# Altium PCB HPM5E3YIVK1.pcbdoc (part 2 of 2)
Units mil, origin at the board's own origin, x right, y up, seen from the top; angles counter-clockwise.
Board outline 3937 x 3149.7 mil, 6 copper layers (Top Layer, Inner1, Inner2, Inner3, Inner4, Bottom Layer), stack 60.7 mil thick; 242 components, 203 nets, 838 pads, 137 vias.
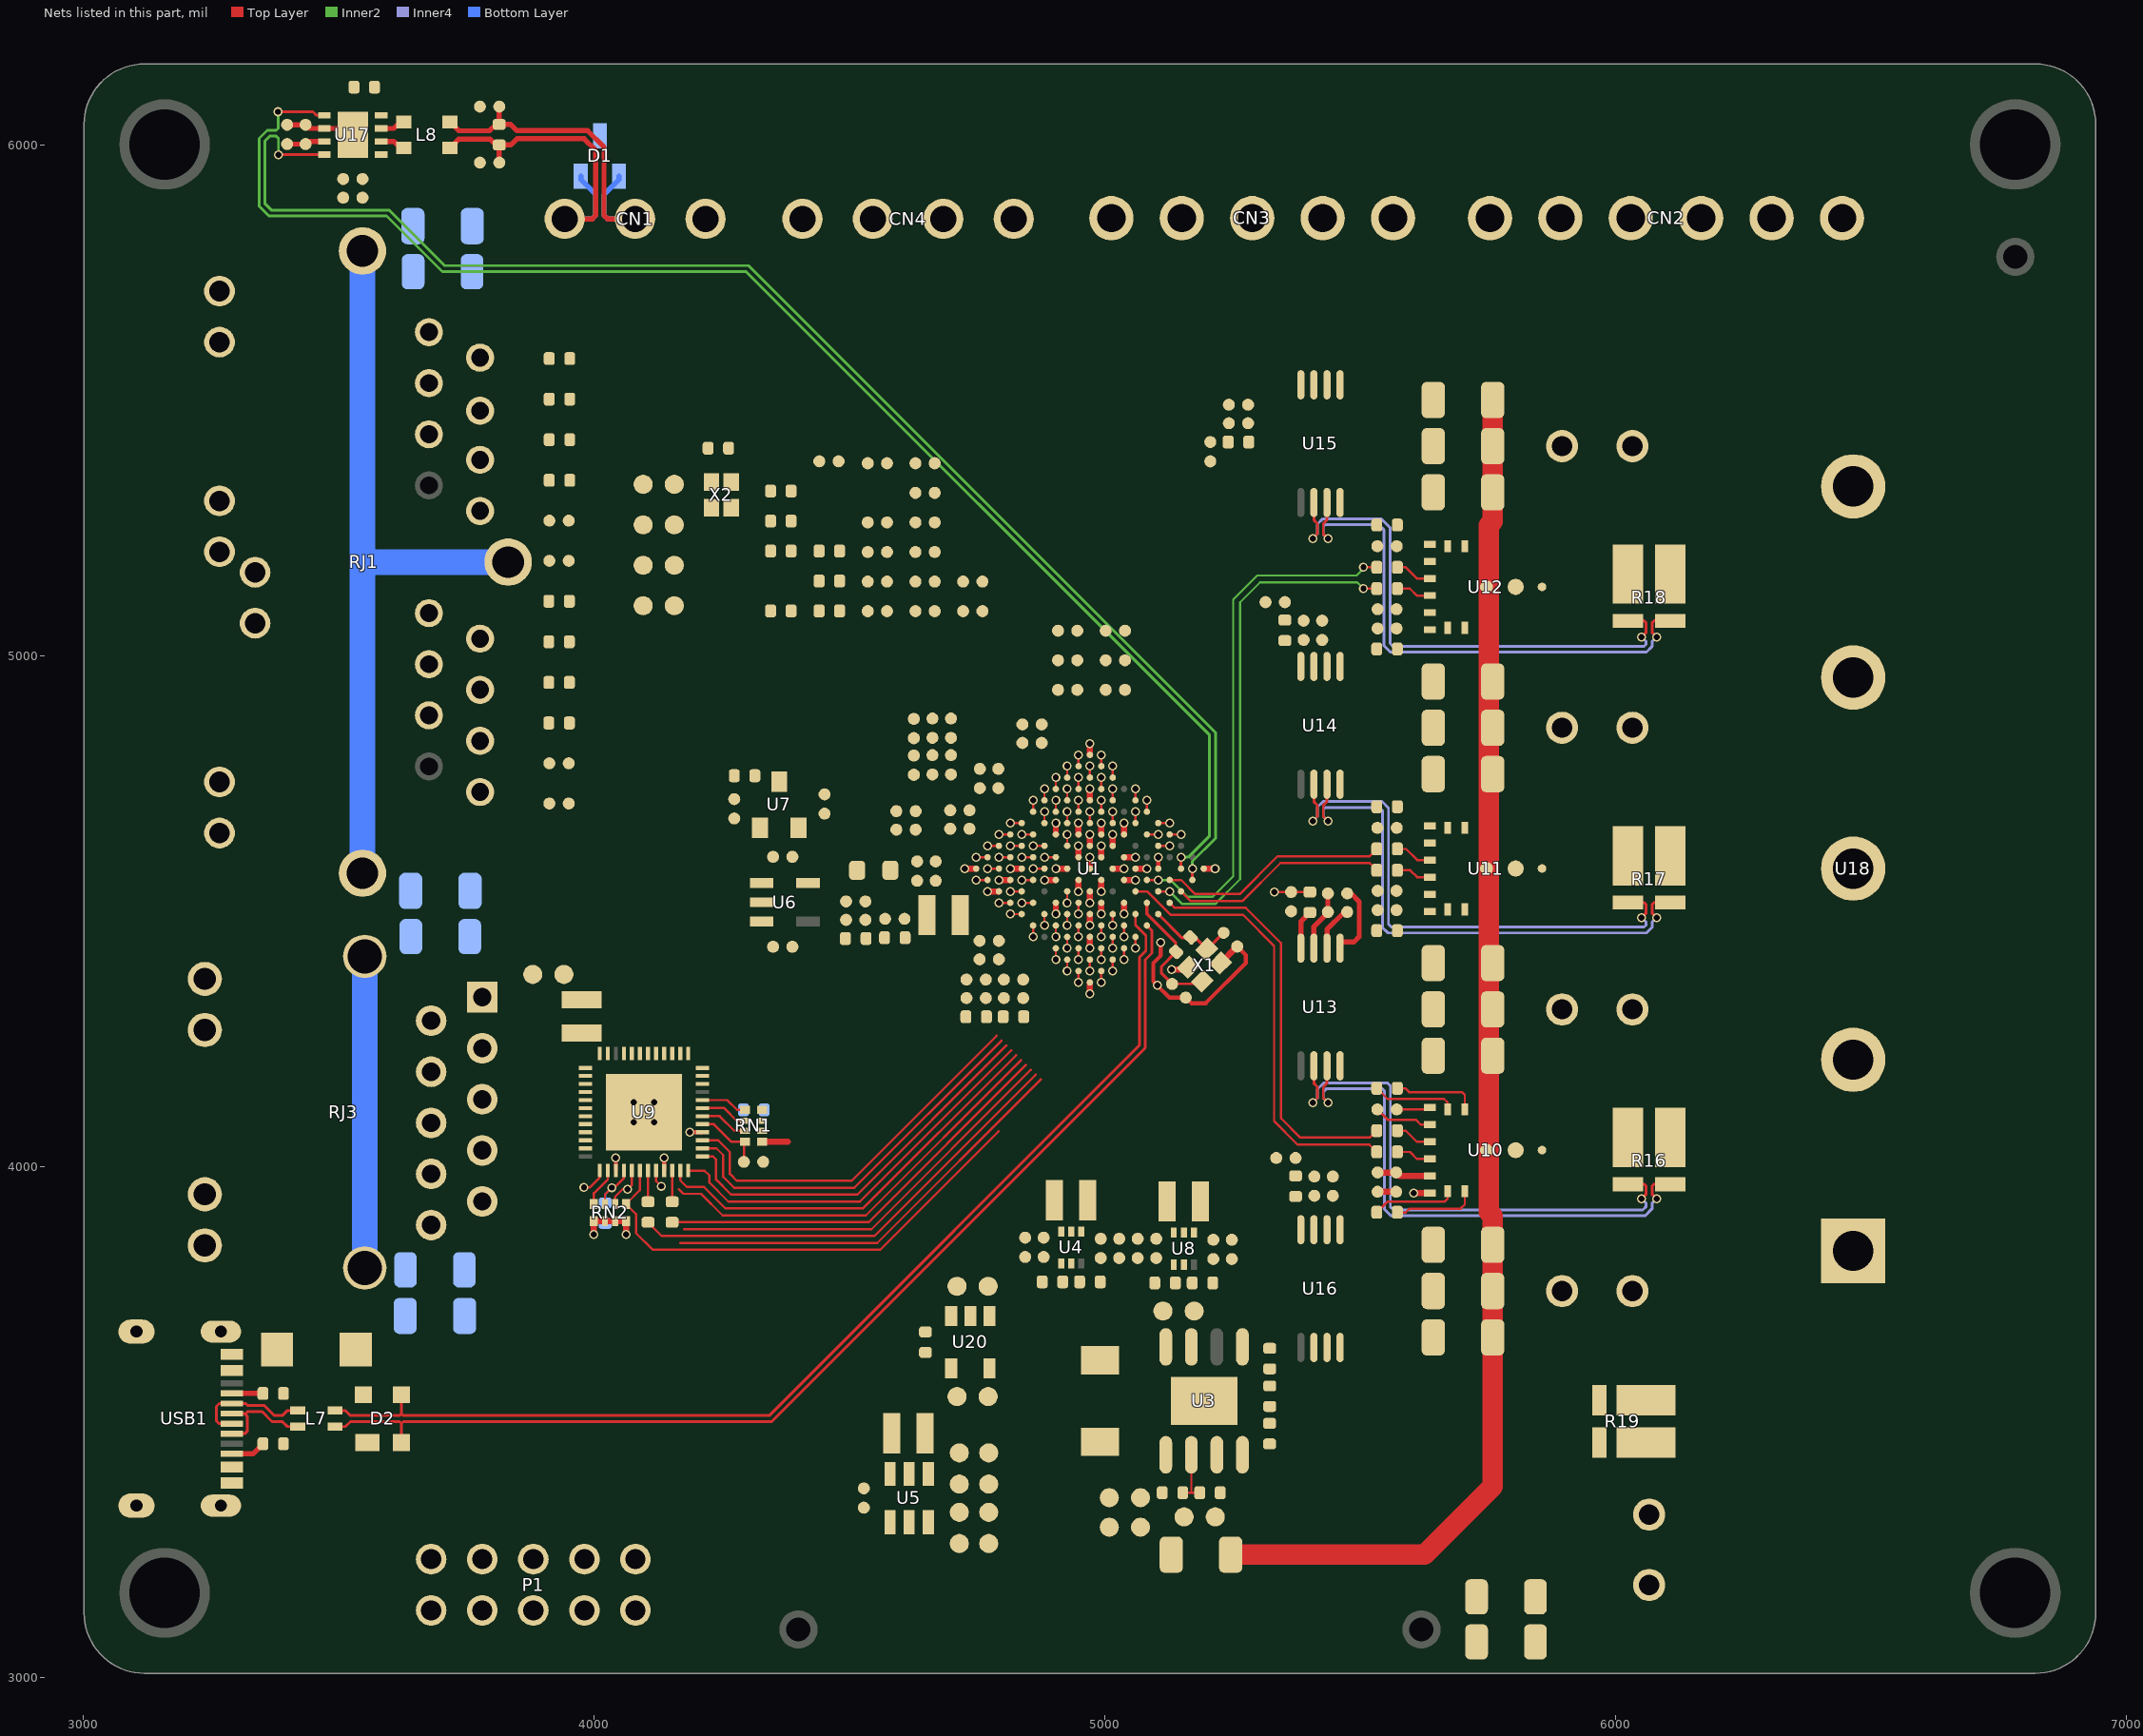
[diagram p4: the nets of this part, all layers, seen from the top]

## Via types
v1: diameter 17.7, hole 12, Top Layer to Bottom Layer, 133 vias
v2: diameter 24, hole 12, Top Layer to Bottom Layer, 4 vias

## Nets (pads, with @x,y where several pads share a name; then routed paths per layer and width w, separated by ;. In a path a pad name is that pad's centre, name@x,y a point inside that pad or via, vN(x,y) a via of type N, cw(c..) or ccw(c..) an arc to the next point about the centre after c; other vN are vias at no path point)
5V: C40.1 C41.1 C125.1 D2.4 D3.1 L3.2 U5.1 U20.5
$1N77: C3.1 C4.1 FB1.1 U1.K2 U1.L2 | length 44.6
  Top Layer w4.5: v1(4748.2,4561.5) U1.L2@4770.5,4561.5 ; v1(4770.5,4583.7) U1.K2@4792.8,4583.7
$1N85: C7.1 C8.1 FB2.1 U1.H6 | length 22.3
  Top Layer w4.5: v1(4926.4,4516.9) U1.H6@4926.4,4539.2
$1N89: C9.1 R3.1
$1N91: C10.1 C11.1 FB3.2 U1.H7 | length 22.2
  Top Layer w4.5: v1(4948.6,4494.7) U1.H7@4948.6,4516.9
$1N106: C26.1 C27.1 U1.H4 | length 22.2
  Top Layer w4.5: v1(4859.6,4583.7) U1.H4@4881.8,4583.7
$1N108: C28.1 C29.1 U1.F4 | length 22.2
  Top Layer w4.5: U1.F4@4926.4,4628.3 v1(4926.4,4650.5)
$1N110: C30.1 C31.1 U1.G4 | length 22.3
  Top Layer w4.5: v1(4881.8,4606) U1.G4@4904.1,4606
$1N112: C32.1 C33.1 U1.D4 | length 22.3
  Top Layer w4.5: U1.D4@4970.9,4672.8 v1(4970.9,4695.1)
$3N8: R5.2 R6.1 U3.2 | length 107.5
  Top Layer w4.5: R6.1@5152.6,3362.3 5168.9,3362.3 ; U3.2@5169.3,3436.5 5169.3,3362.7 5168.9,3362.3 ; R5.2@5185.7,3362.3 5168.9,3362.3
$3N11: R7.1 U3.4
$3N13: C36.1 L2.1 U3.8
$3N15: C36.2 U3.7
$3N18: R8.1 R9.2 U3.5
$3N20: C39.2 L3.1 U5.5
$3N21: C39.1 U5.6
$3N27: L4.1 U4.2
$3N34: R10.2 R11.2 U4.5
$3N48: R12.2 R13.2 U8.5
$3N54: L5.1 U8.2
$3N62: R61.1 U20.3
$4N84: C56.1 RJ1.A4
$4N85: C57.1 RJ1.A5
$4N86: C62.1 RJ1.B4
$4N87: C63.1 RJ1.B5
$4N90: R20.1 RJ1.A9
$4N92: R22.1 RJ1.A11
$4N94: R24.1 RJ1.B9
$4N96: R26.1 RJ1.B11
$5N100: L6.1 U9.48
$5N112: R28.1 U9.38
$5N113: R29.1 U9.39
$5N117: C70.2 R30.2 U9.42 X2.3
$5N150: R31.2 U9.19 | length 60.9
  Top Layer w4.5: R31.2@4106,3931.7 U9.19@4106,3992.6
$5N152: R32.2 U9.22 | length 60.9
  Top Layer w4.5: R32.2@4153.2,3931.7 U9.22@4153.2,3992.6
$5N166: R33.2 RJ3.12
$5N169: R36.2 RJ3.13
$5N190: C80.2 RJ3.P1
$5N214: C71.2 R30.1 U9.43 X2.1
$6N1: R16.2 U10.9
$6N2: R17.2 U11.9
$6N3: R18.2 U12.9
$6N4: C89.2 U10.25 | length 66.1
  Top Layer w4.5: C89.2@5571.3,4112.4 5632,4112.4 U10.25@5635.9,4116.2
$6N5: C89.1 U10.26 | length 114.7
  Top Layer w4.5: C89.1@5533.5,4112.4 5553.5,4092.3 5608.6,4092.3 5618.2,4082.8 U10.26@5635.9,4082.8
$6N6: R43.2 U10.23 | length 165.5
  Top Layer w4.5: R43.2@5572.5,4153.7 5588.2,4153.7 5595.5,4146.4 5698.8,4146.4 5704.5,4140.7 U10.23@5704.5,4112.6
$6N7: R43.1 U10.24 | length 163.6
  Top Layer w4.5: R43.1@5532.3,4153.7 5553.2,4132.9 5664.2,4132.9 5671.1,4126 U10.24@5671.1,4112.6
$6N8: R44.1 U10.1 | length 164.3
  Top Layer w4.5: R44.1@5532.3,3911.2 5552.8,3931.7 5664.4,3931.7 5671.1,3938.3 U10.1@5671.1,3952.6
$6N9: R44.2 U10.2 | length 165.8
  Top Layer w4.5: R44.2@5571.6,3910.5 5588.8,3910.5 5596.4,3918.2 5696.4,3918.2 5704.5,3926.3 U10.2@5704.5,3952.6
$6N26: R47.1 U11.24
$6N27: R48.1 U11.1
$6N28: R47.2 U11.23
$6N29: R48.2 U11.2
$6N30: C91.1 U11.26
$6N31: C91.2 U11.25
$6N39: R51.1 U12.24
$6N40: R52.1 U12.1
$6N41: R51.2 U12.23
$6N42: R52.2 U12.2
$6N43: C93.1 U12.26
$6N44: C93.2 U12.25
$6N51: R45.1 U10.27 | length 72.4
  Top Layer w4.5: R45.1@5572.5,4071 5588.8,4071 5610.5,4049.3 U10.27@5635.9,4049.3
$6N52: R46.1 U10.28 | length 69
  Top Layer w4.5: R46.1@5572.5,4029.3 5597.2,4029.3 5610.7,4015.8 U10.28@5635.9,4015.8
$6N54: R49.1 U11.27 | length 72.4
  Top Layer w4.5: R49.1@5572.5,4622.2 5589.5,4622.2 5611.2,4600.5 U11.27@5635.9,4600.5
$6N55: R50.1 U11.28 | length 69
  Top Layer w4.5: R50.1@5572.5,4580.5 5597.7,4580.5 5611.2,4567 U11.28@5635.9,4567
$6N57: R53.1 U12.27 | length 72.4
  Top Layer w4.5: R53.1@5572.5,5173.4 5589,5173.4 5610.7,5151.7 U12.27@5635.9,5151.7
$6N58: R54.1 U12.28 | length 69
  Top Layer w4.5: R54.1@5572.5,5131.7 5597.1,5131.7 5610.5,5118.2 U12.28@5635.9,5118.2
$7N5: R55.2 U13.8 | length 64.9
  Top Layer w10: U13.8@5383.6,4440.2 5383.6,4480.1 R55.2@5401.2,4497.8
$7N38: C97.1 R55.1 | length 69.2
  Top Layer w4.5: v1(5332,4537.9) C97.1@5364.6,4537.9 R55.1@5401.2,4537.9
$7N41: C100.1 R56.1
$7N49: R56.2 U14.8
$7N52: C103.1 R57.1
$7N60: R57.2 U15.8
$7N63: C106.1 R58.1
$7N71: R58.2 U16.8
$8N9: R59.2 USB1.A5 | length 60.6
  Top Layer w10: USB1.A5@3291.7,3556.6 R59.2@3352.3,3556.6
$8N10: R60.2 USB1.B5 | length 68.8
  Top Layer w10: USB1.B5@3291.7,3438.4 3332.6,3438.4 R60.2@3352.3,3458.1
$8N21: L7.1 USB1.A7 USB1.B7 | length 236.5
  Top Layer w5.5: USB1.A7@3291.7,3497.5 3266.8,3497.5 3261.3,3502.9 3261.3,3531.4 3266.8,3536.9 USB1.B7@3291.7,3536.9 3318.9,3536.9 3323,3532.8 3355.1,3532.8 3374.8,3513.2 3390.3,3513.2 3400.3,3523.2 L7.1@3420.5,3523.2
$8N22: L7.4 USB1.A6 USB1.B6 | length 211.7
  Top Layer w5.5: USB1.B6@3291.7,3477.8 3316.6,3477.8 3322.1,3483.3 3322.1,3511.4 3316.4,3517.2 ; USB1.A6@3291.7,3517.2 3316.4,3517.2 ; L7.4@3420.5,3491.7 3400.3,3491.7 3390.3,3501.7 3370,3501.7 3350.4,3521.3 3323,3521.3 3318.9,3517.2 3316.4,3517.2
$9N1: P1.7
$9N2: P1.3
$9N4: P1.1
$9N5: P1.9
$9N6: P1.5
$9N7: P1.2
$9N8: P1.8
$9N9: P1.10
$9N10: P1.4
$9N11: P1.6
$10N3: R41.2 U17.8
$10N15: L8.2 U17.6 | length 49.2
  Top Layer w10: U17.6@3583.9,6006.8 3608.3,6006.8 3621.1,5994 L8.2@3627.8,5994
$10N16: L8.1 U17.7 | length 49.1
  Top Layer w10: U17.7@3583.9,6032.4 3608.3,6032.4 3621.1,6045.1 L8.1@3627.8,6045.1
+1.0V: C58.1 C59.1 C60.1 C61.1 C66.1 C67.1 C68.1 C69.1 L6.2 U9.3 U9.9 U9.28 U9.36 U9.40 | length 24.9
  Top Layer w8: v1(4187.7,4067.6) 4212.5,4067.6 U9.28@4212.6,4067.7
+1.25V: C54.2 C55.2 L5.2 R12.1
+3.3V: C18.1 C19.1 C20.1 C21.1 C22.1 C23.1 C24.1 C25.1 C46.2 C47.2 C52.1 C53.1 C72.1 C73.1 C74.1 C75.1 C76.1 C77.1 C78.1 C79.1 C83.1 C84.1 FB1.2 L4.2 R10.1 R28.2 R35.2 R38.2 RJ3.14 RN1.1 RN1.2 RN1.3 RN1.4 RN2.1 RN2.2 RN2.3 RN2.4 U1.D7 U1.D8 U1.E4 U1.E8 U1.G8 U1.H5 U8.3 U8.4 U9.6 U9.15 U9.21 U9.37 U9.41 U9.44 U9.45 U17.5 | length 348.8
  Top Layer w8: U9.15@4043,3992.6 v1(4043,4017.4) ; U9.21@4137.5,3992.6 v1(4137.5,4017.5)
  Top Layer w12: v1(4000.1,3867.6) RN2.4@4000.1,3893.7 RN2.3@4021.7,3893.7 RN2.2@4041.4,3893.7 RN2.1@4063.1,3893.7 v1(4063.1,3867.6) ; RN1.4@4329.3,4049 4379.5,4049 ; v1(4881.8,4561.5) U1.H5@4904.1,4561.5 ; U1.E4@4948.6,4650.5 v1(4948.6,4672.8) ; v1(4993.2,4494.7) U1.G8@4993.2,4516.9 ; U1.E8@5037.7,4561.5 v1(5060,4561.5) ; U1.D7@5037.7,4606 v1(5060,4606) ; U1.D8@5060,4583.7 v1(5082.3,4583.7)
+3.3VA: C49.1 C95.1 C98.1 C101.1 C104.1 FB2.2 U6.5 U13.5 U14.5 U15.5 U16.5 | length 140.4
  Top Layer w10: U13.5@5460.4,4440.2 5487.6,4440.2 5497.9,4450.5 5497.9,4518.9 5481.6,4535.2 C95.1@5474.4,4535.2
+3.3VREF: C50.1 C96.1 C99.1 C102.1 C105.1 FB3.1 U7.2 U13.6 U14.6 U15.6 U16.6 | length 78.3
  Top Layer w10: U13.6@5434.8,4440.2 5434.8,4464.8 5468.8,4498.8 C96.1@5474.4,4498.8
+5V: C44.1 C45.1 C48.1 C51.1 C85.1 C86.1 C90.1 C92.1 C94.1 C124.1 C126.1 C127.1 C128.1 CN2.1 CN3.1 CN4.4 U4.3 U4.4 U6.1 U6.3 U7.1 U10.29 U11.29 U12.29 U17.3 U20.1 | length 184
  Top Layer w10: C86.1@3399.6,6001.7 C85.1@3435.8,6001.7 3440.9,6006.8 U17.3@3472.7,6006.8
  Top Layer w12: C126.1@5529.9,3989.1 C90.1@5570.2,3989.1 5576.9,3982.4 U10.29@5635.9,3982.4
+12V: C37.1 C38.1 C42.2 C43.2 L2.2 R8.2 U5.2 U5.3
ADC0.IN00: CN4.3 U1.K8 | length 22.3
  Top Layer w4.5: v1(4926.4,4427.8) U1.K8@4926.4,4450.1
ADC0.IN01: U1.L6 | length 22.3
  Top Layer w4.5: v1(4859.6,4450.1) U1.L6@4859.6,4472.4
ADC0.IN02: U1.J8 | length 22.3
  Top Layer w4.5: v1(4948.6,4450.1) U1.J8@4948.6,4472.4
ADC0.IN03: U1.L5 | length 22.3
  Top Layer w4.5: v1(4815,4494.7) U1.L5@4837.3,4494.7
ADC0.IN08: U1.K6 | length 22.3
  Top Layer w4.5: v1(4881.8,4472.4) U1.K6@4881.8,4494.7
ADC0.IN10: U1.K7 | length 22.3
  Top Layer w4.5: v1(4904.1,4450.1) U1.K7@4904.1,4472.4
ADC0.IN13: CN4.2 U1.K5 | length 22.3
  Top Layer w4.5: v1(4837.3,4516.9) U1.K5@4859.6,4516.9
ADC0.IN14: U1.L8 | length 22.2
  Top Layer w4.5: v1(4904.1,4405.6) U1.L8@4904.1,4427.8
ADC0.IN15: U1.J7 | length 22.2
  Top Layer w4.5: v1(4926.4,4472.4) U1.J7@4926.4,4494.6
AGND: C7.2 C8.2 C10.2 C11.2 C48.2 C49.2 C50.2 C51.2 C95.2 C96.2 C97.2 C98.2 C99.2 C100.2 C101.2 C102.2 C103.2 C104.2 C105.2 C106.2 CN4.1 R4.2 U1.G7 U1.H8 U6.2 U7.3 U13.4 U13.7 U14.4 U14.7 U15.4 U15.7 U16.4 U16.7 | length 150.9
  Top Layer w10: U13.7@5409.2,4440.2 5409.2,4470.1 5436.6,4497.5 C95.2@5436.6,4535.2
  Top Layer w12: v1(4970.9,4472.4) U1.H8@4970.9,4494.7 ; v1(4970.9,4516.9) U1.G7@4970.9,4539.2
BOOT0: U1.C2 | length 22.3
  Top Layer w4.5: U1.C2@4948.6,4739.6 v1(4948.6,4761.9)
BOOT1: U1.B1 | length 22.2
  Top Layer w4.5: U1.B1@4948.6,4784.2 v1(4948.6,4806.4)
CAN_H: C87.2 CN1.2 D1.1 L8.4 R42.1 | length 710.7
  Top Layer w10: L8.4@3718.1,6045.1 3735.7,6027.6 3795.8,6027.6 R42.1@3808.3,6040.1 ; C87.2@3814.9,6075 R42.1@3814.9,6040.1 3837.5,6040.1 3849.6,6028 3987.7,6028 4019.8,5995.9 4019.8,5862.4 4026.9,5855.3 CN1.2@4080.7,5855.3
  Bottom Layer w10: D1.1@4049.2,5939 4049.2,5932.4 4019.8,5903 4019.8,5862.4 4026.9,5855.3 CN1.2@4080.7,5855.3
CAN_L: C88.2 CN1.3 D1.2 L8.3 R42.2 | length 683.6
  Top Layer w10: L8.3@3718.1,5994 3735.7,6011.6 3796.6,6011.6 R42.2@3808.3,5999.9 ; C88.2@3814.9,5965.4 R42.2@3814.9,5999.9 3837.5,5999.9 3849.6,6012 3981.1,6012 4003.8,5989.3 4003.8,5862.4 3996.8,5855.3 CN1.3@3942.9,5855.3
  Bottom Layer w10: CN1.3@3942.9,5855.3 3996.8,5855.3 4003.8,5862.4 4003.8,5903 3974.4,5932.4 D1.2@3974.4,5939
DCDC_GND: C3.2 C4.2 C9.2 R2.2 U1.K3 U1.L3 | length 44.4
  Top Layer w12: v1(4770.5,4539.2) U1.L3@4792.7,4539.2 ; v1(4792.8,4561.5) U1.K3@4815,4561.5
DCDC_LP: L1.2 R3.2 U1.K4 U1.L4 | length 44.5
  Top Layer w4.5: v1(4792.8,4516.9) U1.L4@4815,4516.9 ; v1(4815,4539.2) U1.K4@4837.3,4539.2
ESC0_MDC: RN1.6 U1.D3 U9.30 | length 117.1
  Top Layer w4.5: U9.30@4212.6,4099.2 4246.3,4099.2 4275,4070.6 RN1.6@4295.6,4070.6 ; U1.D3@4948.6,4695.1 v1(4948.6,4717.4)
ESC0_MDIO: RN1.7 U1.D2 U9.31 | length 115.4
  Top Layer w4.5: U9.31@4212.6,4115 4255,4115 4279.7,4090.3 RN1.7@4295.6,4090.3 ; U1.D2@4926.4,4717.4 v1(4926.4,4739.6)
ESC0_P0_LED0: R25.1 RJ1.B10 U1.E3 | length 22.3
  Top Layer w4.5: U1.E3@4926.4,4672.8 v1(4926.4,4695.1)
ESC0_P0_LED1: R26.2 R27.2 U1.E2 | length 22.3
  Top Layer w4.5: U1.E2@4904.1,4695.1 v1(4904.1,4717.4)
ESC0_P0_RB: U1.E1 | length 22.2
  Top Layer w4.5: U1.E1@4881.8,4717.4 v1(4881.8,4739.6)
ESC0_P0_RXN: RJ1.B6 U1.H2 | length 22.3
  Top Layer w4.5: v1(4815,4628.3) U1.H2@4837.3,4628.3
ESC0_P0_RXP: RJ1.B3 U1.H3 | length 22.3
  Top Layer w4.5: v1(4837.3,4606) U1.H3@4859.6,4606
ESC0_P0_TXN: RJ1.B2 U1.G1 | length 22.3
  Top Layer w4.5: v1(4815,4672.8) U1.G1@4837.3,4672.8
ESC0_P0_TXP: RJ1.B1 U1.G2 | length 22.3
  Top Layer w4.5: v1(4837.3,4650.5) U1.G2@4859.6,4650.5
ESC0_P1_LED0: R20.2 R21.2 U1.F2 | length 22.3
  Top Layer w4.5: U1.F2@4881.8,4672.8 v1(4881.8,4695.1)
ESC0_P1_LED1: R23.1 RJ1.A12 U1.F1 | length 22.3
  Top Layer w4.5: U1.F1@4859.6,4695.1 v1(4859.6,4717.4)
ESC0_P1_RB: U1.G3 | length 22.2
  Top Layer w4.5: v1(4859.6,4628.3) U1.G3@4881.8,4628.3
ESC0_P1_RXN: RJ1.A6 U1.K1 | length 22.3
  Top Layer w4.5: v1(4748.2,4606) U1.K1@4770.5,4606
ESC0_P1_RXP: RJ1.A3 U1.J1 | length 22.2
  Top Layer w4.5: v1(4770.5,4628.3) U1.J1@4792.7,4628.3
ESC0_P1_TXN: RJ1.A2 U1.J2 | length 22.2
  Top Layer w4.5: v1(4792.8,4606) U1.J2@4815,4606
ESC0_P1_TXP: RJ1.A1 U1.H1 | length 22.2
  Top Layer w4.5: v1(4792.8,4650.5) U1.H1@4815,4650.5
ETH0.G0-EXDLY: R40.1 RN1.8 U9.32 | length 90.7
  Top Layer w4.5: U9.32@4212.6,4130.7 4261.2,4130.7 4279.9,4112 RN1.8@4295.6,4112
ETH0.INTB: R38.1 U1.C4 U9.20 | length 56.8
  Top Layer w4.5: U9.20@4121.7,3992.6 4121.7,3972.2 v1(4131.7,3962.2) ; U1.C4@4993.2,4695.1 v1(4993.2,4717.4)
ETH0.LED0: R34.2 RJ3.11 U9.34
ETH0.LED1: R35.1 R36.1 U9.35
ETH0.RST: C82.2 RN1.5 U1.C5 U9.29 | length 159.5
  Top Layer w4.5: U9.29@4212.6,4083.5 4235,4083.5 4269.6,4049 RN1.5@4295.6,4049 4293.6,4046.9 C82.2@4293.6,4009.9 ; U1.C5@5015.5,4672.8 v1(5015.5,4695.1)
ETH0.RXCK: R31.1 U1.J11 | length 923.1
  Top Layer w4.5: R31.1@4106,3891.6 4133,3864.6 4548.9,3864.6 4864.8,4180.5 ; v1(5015.5,4383.3) U1.J11@5015.5,4405.6
ETH0.RXD0: RN2.5 U1.H10 U9.14 | length 98.7
  Top Layer w4.5: RN2.5@4000.1,3927.4 4000.1,3948.4 4027.2,3975.5 U9.14@4027.2,3992.6 ; v1(5015.5,4427.8) U1.H10@5015.5,4450.1
ETH0.RXD1: R39.1 RN2.6 U1.L9 U9.16 | length 141.4
  Top Layer w4.5: RN2.6@4021.7,3927.4 4021.7,3945.9 v1(4035.3,3959.4) 4040.4,3959.4 4058.7,3977.8 U9.16@4058.7,3992.6 ; v1(4926.4,4383.3) U1.L9@4926.4,4405.6
  Bottom Layer w4.5: R39.1@4022.1,3929.3 4022.1,3946.2 v1(4035.3,3959.4)
ETH0.RXD2: RN2.7 U1.G10 U9.17 | length 107.5
  Top Layer w4.5: RN2.7@4041.4,3927.4 4041.4,3941.4 4057.5,3957.4 4065.1,3957.4 v1(4066,3956.5) 4074.5,3965 U9.17@4074.5,3992.6 ; v1(5037.7,4450.1) U1.G10@5037.7,4472.4
ETH0.RXD3: RN2.8 U1.K10 U9.18 | length 982.6
  Top Layer w4.5: U9.18@4090.2,3992.6 4090.2,3954.5 RN2.8@4063.1,3927.4 4082.5,3907.9 4082.5,3870.5 4115.5,3837.6 4560.1,3837.6 4791.9,4069.4 ; v1(4970.9,4383.3) U1.K10@4970.9,4405.6
ETH0.RXDV: U1.G11 U9.13 | length 74.5
  Top Layer w4.5: v1(3980.7,3960.2) 3992.8,3960.2 4011.5,3978.9 U9.13@4011.5,3992.6 ; v1(5060,4427.8) U1.G11@5060,4450.1
ETH0.RXER: U1.K9 | length 22.2
  Top Layer w4.5: v1(4948.6,4405.6) U1.K9@4948.6,4427.8
ETH0.TXCK: R32.1 U1.L10 | length 842.4
  Top Layer w4.5: R32.1@4153.2,3891.6 4537.7,3891.6 4845.7,4199.6 ; v1(4948.6,4361) U1.L10@4948.6,4383.3
ETH0.TXD0: U1.J10 U9.23 | length 845.7
  Top Layer w4.5: U9.23@4169,3992.6 4169,3973.9 4182.1,3960.8 4215.4,3960.8 4257.6,3918.6 4526.5,3918.6 4826.6,4218.7 ; v1(4993.2,4405.6) U1.J10@4993.2,4427.8
ETH0.TXD1: U1.H9 U9.24 | length 810.5
  Top Layer w4.5: U9.24@4184.7,3992.6 4216.5,3992.6 4225.9,3983.3 4225.9,3969.4 4263.2,3932.1 4520.9,3932.1 4817.1,4228.2 ; v1(4993.2,4450.1) U1.H9@4993.2,4472.4
ETH0.TXD2: U1.G9 U9.25 | length 792.2
  Top Layer w4.5: U9.25@4212.6,4020.5 4233.2,4020.5 4239.4,4014.3 4239.4,3975 4268.8,3945.6 4515.4,3945.6 4807.5,4237.8 ; v1(5015.5,4472.4) U1.G9@5015.5,4494.6
ETH0.TXD3: U1.K11 U9.26 | length 784
  Top Layer w4.5: U9.26@4212.6,4036.2 4239.9,4036.2 4252.9,4023.3 4252.9,3980.6 4274.4,3959.1 4509.8,3959.1 4798,4247.3 ; v1(4993.2,4361) U1.K11@4993.2,4383.3
ETH0.TXEN: U1.H11 U9.27 | length 773.7
  Top Layer w4.5: U9.27@4212.6,4052 4243.3,4052 4266.4,4028.9 4266.4,3986.2 4280,3972.6 4504.2,3972.6 4788.4,4256.9 ; v1(5037.7,4405.6) U1.H11@5037.7,4427.8
GND: C1.2 C2.2 C5.2 C6.2 C12.2 C13.2 C14.2 C15.2 C16.2 C17.2 C18.2 C19.2 C20.2 C21.2 C22.2 C23.2 C24.2 C25.2 C26.2 C27.2 C28.2 C29.2 C30.2 C31.2 C32.2 C33.2 C34.2 C35.2 C37.2 C38.2 C40.2 C41.2 C42.1 C43.1 C44.2 C45.2 C46.1 C47.1 C52.2 C53.2 C54.1 C55.1 C56.2 C57.2 C58.2 C59.2 C60.2 C61.2 C62.2 C63.2 C64.2 C65.2 C66.2 C67.2 C68.2 C69.2 C70.1 C71.1 C72.2 C73.2 C74.2 C75.2 C76.2 C77.2 C78.2 C79.2 C80.1 C81.2 C82.1 C83.2 C84.2 C85.2 C86.2 C87.1 C88.1 C90.2 C92.2 C94.2 C124.2 C125.2 C126.2 C127.2 C128.2 CN1.1 CN2.6 CN3.5 D1.3 D2.1 R2.1 R4.1 R6.2 R7.2 R9.1 R11.1 R13.1 R14.1 R15.1 R22.2 R23.2 R24.2 R25.2 R29.2 R33.1 R34.1 R37.1 R39.2 R40.2 R41.1 R59.1 R60.1 R61.2 R62.2 R63.2 RJ1.A8 RJ1.B8 RJ3.P10 U1.A1 U1.A11 U1.C3 U1.C6 U1.C9 U1.E6 U1.E7 U1.F3 U1.F6 U1.F7 U1.F9 U1.G6 U1.J3 U1.J6 U1.J9 U1.L1 U1.L11 U3.1 U3.9 U4.1 U5.4 U8.1 U9.47 U9.49 U17.2 U17.9 U20.2 U20.4 USB1.13 USB1.14 USB1.A1B12 USB1.B1A12 X1.2 X1.4 X2.2 X2.4 | length 3452.1
  Top Layer w4.5: 4166.7,3956 4175.4,3947.3 4209.8,3947.3 4252,3905.1 4532.1,3905.1 4836.2,4209.1 ; 4169.1,3851.1 4554.5,3851.1 4874.4,4171 ; 4176.6,3878.1 4543.3,3878.1 4855.3,4190
  Top Layer w8: U1.C9@5104.5,4583.7 v1(5104.5,4606) ; v1(5109.6,4438.9) 5109.6,4413.5 5094.9,4398.8 5094.9,4362.9 v1(5102.5,4355.2) 5126.4,4331.3 C1.2@5158.4,4331.3 5169.4,4320.3 5197.5,4320.3 5276.1,4398.8 5276.1,4414.5 C2.2@5259.2,4431.3
  Top Layer w10: C86.2@3399.6,6039.5 C85.2@3435.8,6039.5 3443,6032.4 U17.2@3472.7,6032.4 3515.5,6032.4 U17.9@3528.3,6019.6
  Top Layer w12: v1(4725.9,4583.7) U1.L1@4748.2,4583.7 ; v1(4815,4583.7) U1.J3@4837.3,4583.7 ; v1(4904.1,4494.7) U1.J6@4904.1,4516.9 ; U1.F3@4904.1,4650.5 v1(4904.1,4672.8) ; v1(4948.6,4539.2) U1.G6@4948.6,4561.5 ; v1(4970.9,4338.8) U1.L11@4970.9,4361 ; v1(4970.9,4427.8) U1.J9@4970.9,4450.1 ; U1.F6@4970.9,4583.7 v1(4970.9,4606) ; U1.C3@4970.9,4717.4 v1(4970.9,4739.6) ; U1.A1@4970.9,4806.4 v1(4970.9,4828.7) ; v1(4993.2,4539.2) U1.F7@4993.2,4561.5 ; U1.E6@4993.2,4606 v1(4993.2,4628.3) ; U1.E7@5015.5,4583.7 v1(5037.7,4583.7) ; v1(5037.7,4494.7) U1.F9@5037.7,4516.9 ; U1.C6@5037.7,4650.5 v1(5037.7,4672.8) ; v1(5130.5,4386.3) 5159.5,4386.3 X1.2@5163.7,4390.5 ; U1.A11@5193.6,4583.7 v1(5215.9,4583.7) ; X1.4@5226.4,4398.9 5258.8,4431.3 C2.2@5259.2,4431.3 ; C126.2@5529.9,3951.3 C90.2@5570.2,3951.3
  other v2: 4078.4,4087.4 4117.8,4087.4 4078.4,4126.8 4117.8,4126.8
GND_ESC: C64.1 C65.1 R14.2 R15.2 RJ1.S1 RJ1.S2 RJ1.S3 | length 1503.3
  Bottom Layer w50: RJ1.S2@3547.2,4574.8 3547.2,5182.7 ; RJ1.S1@3547.2,5792.6 3547.2,5182.7 ; RJ1.S3@3832.3,5183.7 3548.2,5183.7 3547.2,5182.7
GND_ETH: C81.1 R37.2 RJ3.SHIELD0 RJ3.SHIELD1 | length 609.8
  Bottom Layer w50: RJ3.SHIELD0@3551.6,3802.2 RJ3.SHIELD1@3551.6,4412
IN_VBUS+: R19.3 U16.2
IN_VBUS-: R19.4 U16.3
INU+: R16.4 U13.2 | length 1086.9
  Top Layer w5.5: v1(5407.2,4125.3) 5416.2,4134.3 5416.2,4156.6 5409.2,4163.6 U13.2@5409.2,4197.8 ; R16.4@6023.9,3966.2 6055.6,3966.2 6059.5,3962.3 6059.5,3946.8 v1(6050.5,3937.8)
  Inner4 w5.5: v1(5407.2,4125.3) 5416.2,4134.3 5416.2,4152 5428.5,4164.2 5553.4,4164.2 5558.9,4158.7 5558.9,3921.7 5564.9,3915.7 6052.7,3915.7 6059.5,3922.5 6059.5,3928.8 v1(6050.5,3937.8)
INU-: R16.3 U13.3 | length 1084
  Top Layer w5.5: U13.3@5434.8,4197.8 5434.8,4163.6 5427.7,4156.6 5427.7,4134.3 v1(5436.7,4125.3) ; v1(6080,3937.8) 6071,3946.8 6071,3962.3 6074.9,3966.2 R16.3@6106.6,3966.2
  Inner4 w5.5: v1(5436.7,4125.3) 5427.7,4134.3 5427.7,4147.2 5433.2,4152.7 5543.5,4152.7 5547.4,4148.8 5547.4,3916.9 5560.2,3904.2 6057.4,3904.2 6071,3917.8 6071,3928.8 v1(6080,3937.8)
INV+: R17.4 U14.2 | length 1079.6
  Top Layer w5.5: v1(5407.2,4676.5) 5416.2,4685.5 5416.2,4707.8 5409.2,4714.8 U14.2@5409.2,4748.9 ; R17.4@6023.9,4517.4 6055.6,4517.4 6059.5,4513.5 6059.5,4497 v1(6050.5,4488)
  Inner4 w5.5: v1(5407.2,4676.5) 5416.2,4685.5 5416.2,4704.1 5427.2,4715 5542.6,4715 5555.2,4702.4 5555.2,4474.9 5560.7,4469.4 6055.6,4469.4 6059.5,4473.2 6059.5,4478.9 v1(6050.5,4488)
INV-: R17.3 U14.3 | length 1080.8
  Top Layer w5.5: U14.3@5434.8,4748.9 5434.8,4714.8 5427.7,4707.8 5427.7,4685.5 v1(5436.7,4676.5) ; v1(6080,4488) 6071,4497 6071,4513.5 6074.9,4517.4 R17.3@6106.6,4517.4
  Inner4 w5.5: v1(5436.7,4676.5) 5427.7,4685.5 5427.7,4699.3 5432,4703.5 5537.9,4703.5 5543.7,4697.7 5543.7,4468.3 5554.1,4457.9 6060.3,4457.9 6071,4468.5 6071,4478.9 v1(6080,4488)
INW+: R18.4 U15.2 | length 1080.5
  Top Layer w5.5: v1(5407.2,5229.8) 5416.2,5238.8 5416.2,5259 5409.2,5266 U15.2@5409.2,5300.1 ; R18.4@6023.9,5068.6 6055.6,5068.6 6059.5,5064.7 6059.5,5046.1 v1(6050.5,5037.1)
  Inner4 w5.5: v1(5407.2,5229.8) 5416.2,5238.8 5416.2,5257.8 5426.9,5268.5 5540.6,5268.5 5558.2,5250.9 5558.2,5024.4 5563.7,5018.9 6055.4,5018.9 6059.5,5023.1 6059.5,5028.1 v1(6050.5,5037.1)
INW-: R18.3 U15.3 | length 1082.2
  Top Layer w5.5: U15.3@5434.8,5300.1 5434.8,5266 5427.7,5259 5427.7,5238.8 v1(5436.7,5229.8) ; v1(6080,5037.1) 6071,5046.1 6071,5064.7 6074.9,5068.6 R18.3@6106.6,5068.6
  Inner4 w5.5: v1@5436.7,5228.1 5427.7,5237.2 5427.7,5253.1 5431.6,5257 5535.8,5257 5546.7,5246.1 5546.7,5019.7 5558.9,5007.4 6060.1,5007.4 6071,5018.3 6071,5028.1 v1(6080,5037.1)
JTAG.TCK: U1.B4 | length 22.2
  Top Layer w4.5: U1.B4@5015.5,4717.4 v1(5015.5,4739.6)
JTAG.TDI: U1.B3 | length 22.3
  Top Layer w4.5: U1.B3@4993.2,4739.6 v1(4993.2,4761.9)
JTAG.TDO: U1.B2 | length 22.3
  Top Layer w4.5: U1.B2@4970.9,4761.9 v1(4970.9,4784.2)
JTAG.TMS: U1.A2 | length 22.2
  Top Layer w4.5: U1.A2@4993.2,4784.2 v1(4993.2,4806.4)
JTAG.TRST: U1.A3 | length 22.3
  Top Layer w4.5: U1.A3@5015.5,4761.9 v1(5015.5,4784.2)
MCAN0.RXD: U1.B11 U17.4 | length 2872.7
  Top Layer w5.5: v1(3382.7,5980.9) 3472.4,5980.9 U17.4@3472.7,5981.2 ; U1.B11@5171.4,4561.5 v1(5171.4,4583.7)
  Inner2 w5.5: v1(3382.7,5980.9) 3382.7,6012.6 3378.1,6017.1 3365.6,6017.1 3356.5,6008.1 3356.5,5884.8 3368.7,5872.6 3599.2,5872.6 3708,5763.8 4302.6,5763.8 5216.6,4849.8 5216.6,4643.1 5171.4,4597.9 v1(5171.4,4583.7)
MCAN0.TXD: U1.B10 U17.1 | length 2885.6
  Top Layer w5.5: v1(3382,6064.9) 3450.1,6064.9 3457.1,6057.9 U17.1@3472.7,6057.9 ; U1.B10@5149.1,4583.7 v1(5149.1,4606)
  Inner2 w5.5: v1(3382,6064.9) 3382,6032.5 3378.1,6028.6 3360.8,6028.6 3345,6012.9 3345,5880 3364,5861.1 3594.5,5861.1 3703.3,5752.3 4297.8,5752.3 5205.1,4845 5205.1,4647.8 5163.2,4606 v1(5149.1,4606)
MDI0_N: RJ3.P3 U9.2
MDI0_P: RJ3.P2 U9.1
MDI1_N: RJ3.P7 U9.5
MDI1_P: RJ3.P4 U9.4
MDI2_N: RJ3.P6 U9.8
MDI2_P: RJ3.P5 U9.7
MDI3_N: RJ3.P9 U9.11
MDI3_P: RJ3.P8 U9.10
PGND: C107.1 C108.1 C109.1 C110.1 C111.1 C112.1 C113.1 C114.1 C115.1 C116.1 C117.1 C118.1 C119.2 C120.2 C121.2 C122.2 C123.2 R62.1 R63.1 U10.5 U10.30 U11.5 U11.30 U12.5 U12.30 U18.2 | length 31.8
  Top Layer w12: v1(5604.1,3948.9) U10.30@5635.9,3948.9
PWM0.P02: R49.2 U1.C10 | length 453.4
  Top Layer w4.5: U1.C10@5126.8,4561.5 5149.3,4561.5 5176.8,4534 5264.1,4534 5338.2,4608.1 5518.2,4608.1 R49.2@5532.3,4622.2
PWM0.P03: R50.2 U1.C11 | length 427.5
  Top Layer w4.5: U1.C11@5149.1,4539.2 5167.8,4520.5 5269.7,4520.5 5343.8,4594.6 5518.2,4594.6 R50.2@5532.3,4580.5
PWM0.P04: R53.2 U1.D9 | length 1049.6
  Top Layer w4.5: U1.D9@5082.3,4561.5 v1(5104.5,4561.5) ; v1(5506.3,5173.4) R53.2@5532.3,5173.4
  Inner2 w4.5: v1(5104.5,4561.5) 5128.7,4561.5 5161.7,4528.5 5211,4528.5 5251.2,4568.7 5251.2,5110.4 5298.2,5157.4 5492.9,5157.4 5506.3,5170.8 v1(5506.3,5173.4)
PWM0.P05: R54.2 U1.D10 | length 1020.7
  Top Layer w4.5: U1.D10@5104.5,4539.2 v1(5126.8,4539.2) ; v1(5506.3,5131.7) R54.2@5532.3,5131.7
  Inner2 w4.5: v1(5126.8,4539.2) 5151,4515 5216.6,4515 5264.7,4563.1 5264.7,5104.8 5303.8,5143.9 5494.1,5143.9 v1(5506.3,5131.7)
PWM0.P06: R45.2 U1.D11 | length 802.5
  Top Layer w4.5: U1.D11@5126.8,4516.9 5136.7,4507 5275.9,4507 5344.8,4438.1 5344.8,4095.1 5382.6,4057.3 5518.6,4057.3 R45.2@5532.3,4071
PWM0.P07: R46.2 U1.E9 | length 884.4
  Top Layer w4.5: U1.E9@5060,4539.2 5082.9,4539.2 5128.6,4493.5 5270.3,4493.5 5331.3,4432.5 5331.3,4089.6 5377.1,4043.8 5517.8,4043.8 R46.2@5532.3,4029.3
QEI1.A: CN3.2 U1.A5 | length 22.2
  Top Layer w4.5: U1.A5@5060,4717.4 v1(5060,4739.6)
QEI1.B: CN3.3 U1.A6 | length 22.3
  Top Layer w4.5: U1.A6@5082.3,4695.1 v1(5082.3,4717.4)
QEI1.Z: CN3.4 U1.B6 | length 22.3
  Top Layer w4.5: U1.B6@5060,4672.8 v1(5060,4695.1)
RSTN: U1.J4 | length 22.3
  Top Layer w4.5: v1(4837.3,4561.5) U1.J4@4859.6,4561.5
SPI1.CS1: CN2.2 U1.B7 | length 22.2
  Top Layer w4.5: U1.B7@5082.3,4650.5 v1(5104.5,4650.5)
SPI1.MISO: CN2.4 U1.B8 | length 22.3
  Top Layer w4.5: U1.B8@5104.5,4628.3 v1(5126.8,4628.3)
SPI1.MOSI: CN2.3 U1.A8 | length 22.3
  Top Layer w4.5: U1.A8@5126.8,4650.5 v1(5149.1,4650.5)
SPI1.SCLK: CN2.5 U1.A7 | length 22.3
  Top Layer w4.5: U1.A7@5104.5,4672.8 v1(5126.8,4672.8)
U: R16.1 U18.3
UART0.RXD: U1.D1 | length 22.3
  Top Layer w4.5: U1.D1@4904.1,4739.6 v1(4904.1,4761.9)
UART0.TXD: U1.C1 | length 22.3
  Top Layer w4.5: U1.C1@4926.4,4761.9 v1(4926.4,4784.2)
USB0.DN: D2.3 L7.2 U1.F10 | length 2189.8
  Top Layer w5.5: L7.2@3493.4,3523.2 3513.6,3523.2 3523.6,3513.2 3619.6,3513.2 3623.5,3517.1 ; D2.3@3623.5,3554.3 3623.5,3517.1 ; U1.F10@5060,4494.7 5060,4473.4 5080.5,4452.9 5080.5,4423 5067.6,4410.1 5067.6,4237.5 4343.3,3513.2 3627.4,3513.2 3623.5,3517.1
USB0.DP: D2.2 L7.3 U1.F11 | length 2182.1
  Top Layer w5.5: L7.3@3493.4,3491.7 3513.6,3491.7 3523.6,3501.7 3619.6,3501.7 3623.5,3497.8 ; D2.2@3623.5,3460.5 3623.5,3497.8 ; U1.F11@5082.3,4472.4 5092,4462.6 5092,4418.2 5079.1,4405.3 5079.1,4232.8 4348,3501.7 3627.4,3501.7 3623.5,3497.8
USB_VBUS: D3.2 USB1.A4B9 USB1.B4A9
V: R17.1 U18.4
VBUS: C34.1 C35.1 C107.2 C108.2 C109.2 C110.2 C111.2 C112.2 C113.2 C114.2 C115.2 C116.2 C117.2 C118.2 C119.1 C120.1 C121.1 C122.1 C123.1 R5.1 R19.2 U3.3 U10.3 U11.3 U12.3 | length 2700.6
  Top Layer w40: C34.1@5246.2,3241.2 5626,3241.2 5759.1,3374.2 C118.2@5759.1,3666.3 C117.2@5759.1,3757 C116.2@5759.1,3847.4 5759.1,3904.5 5752,3911.6 5752,5255.8 5759.1,5262.9 C107.2@5759.1,5319.9 C108.2@5759.1,5410.5 C109.2@5759.1,5501
VBUS_IN: R19.1 U18.1
VCC: R21.1 R27.1 RJ1.A10 RJ1.B12
VCC_SOC: C5.1 C6.1 C12.1 C13.1 C14.1 C15.1 C16.1 C17.1 L1.1 U1.D5 U1.D6 U1.E5 U1.F5 U1.G5 | length 111.3
  Top Layer w12: v1(4904.1,4583.7) U1.G5@4926.4,4583.7 ; U1.F5@4948.6,4606 v1(4948.6,4628.3) ; U1.E5@4970.9,4628.3 v1(4970.9,4650.5) ; U1.D5@4993.2,4650.5 v1(4993.2,4672.8) ; U1.D6@5015.5,4628.3 v1(5015.5,4650.5)
W: R18.1 U18.5
XTALI: C1.1 R1.1 U1.E10 X1.3 | length 264.5
  Top Layer w4.5: C1.1@5131.7,4358 5185.5,4358 X1.3@5190.8,4363.4
  Top Layer w6: U1.E10@5082.3,4516.9 5082.3,4495.3 5138.5,4439.1 R1.1@5138.5,4420.3 ; C1.1@5131.7,4358 5110.9,4378.8 5110.9,4392.2 R1.1@5139.5,4420.8
XTALO: C2.1 R1.2 U1.E11 X1.1 | length 168.9
  Top Layer w6: U1.E11@5104.5,4494.7 5150.5,4448.7 R1.2@5166.9,4448.7 ; R1.2@5167.9,4449.2 5176.1,4449.2 X1.1@5199.2,4426.1 5200.5,4426.1 C2.1@5232.5,4458.1
pads on no net: H1.1 H2.1 H3.1 H4.1 RJ1.A7 RJ1.B7 U1.A4 U1.A9 U1.A10 U1.B5 U1.B9 U1.C7 U1.C8 U1.F8 U1.J5 U1.L7 U2.1 U3.6 U4.6 U6.4 U8.6 U9.12 U9.33 U9.46 U13.1 U14.1 U15.1 U16.1 U19.1 U21.1 USB1.A8 USB1.B8

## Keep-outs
Board Outline Layer:
  the board outline again, w10

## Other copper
Top Layer:
  drawing of 435 lines, arcs and shapes, not listed
Inner2:
  region net PWM0.P05: 5136.9,4532.3 5133.7,4529.1 5132.9,4529.4 5131.1,4529.8 5126.2,4530.4 5135.6,4539.7 5136.2,4534.9 5136.6,4533.1
  region net PWM0.P04: 5116.6,4563.7 5116.6,4559.2 5115.7,4558.8 5114.2,4557.8 5110.4,4554.8 5110.4,4568.1 5114.2,4565.1 5115.7,4564.1
  region net MCAN0.TXD: 3384.8,6052.8 3379.3,6052.8 3378.9,6053.9 3378,6055.5 3376.8,6057.3 3375.4,6059 3388.7,6059 3387.2,6057.3 3386,6055.5 3385.1,6053.9
  region net MCAN0.RXD: 3379.9,5992.9 3385.4,5992.9 3385.8,5991.9 3386.7,5990.3 3387.9,5988.5 3389.3,5986.7 3376,5986.7 3377.5,5988.5 3378.7,5990.3 3379.6,5991.9
  region net PWM0.P05: 5496.2,5138.6 5499.4,5141.8 5500.3,5141.4 5502.1,5141.1 5506.9,5140.5 5497.5,5131.1 5496.9,5135.9 5496.6,5137.7
  region net PWM0.P04: 5501.8,5163 5496.6,5164.3 5497,5164.8 5497.2,5165.5 5497.6,5167.4 5497.7,5169.7 5497.6,5172.1 5508.7,5164.9 5507.3,5164.7 5505.4,5164.5 5503.4,5164 5502.5,5163.6
  region net MCAN0.TXD: 5161.1,4608.7 5161.1,4603.2 5160.1,4602.9 5158.5,4602 5156.7,4600.8 5154.9,4599.3 5154.9,4612.6 5156.7,4611.2 5158.5,4610 5160.1,4609.1
  region net MCAN0.RXD: 5168.6,4595.8 5174.1,4595.8 5174.4,4594.8 5175.3,4593.2 5176.6,4591.4 5178,4589.6 5164.7,4589.6 5166.1,4591.4 5167.4,4593.2 5168.3,4594.8
Inner4:
  region net INW+: 6060.9,5030.5 6057,5026.6 6056.1,5027.1 6054.3,5027.6 6052.2,5028 6049.9,5028.3 6059.3,5037.7 6059.5,5035.4 6060,5033.2 6060.4,5031.5
  region net INW-: 6073.4,5026.6 6069.5,5030.5 6070,5031.5 6070.5,5033.2 6070.9,5035.4 6071.1,5037.7 6080.5,5028.3 6078.3,5028 6076.1,5027.6 6074.4,5027.1
  region net INW-: 5426.1,5234.9 5429.7,5239.1 5430.5,5238.8 5432,5238.6 5436.2,5238.6 5428,5228.1 5427,5232.5 5426.5,5234.1
  region net INW+: 5413.8,5240.2 5417.7,5236.3 5417.2,5235.4 5416.7,5233.6 5416.3,5231.5 5416.1,5229.2 5406.7,5238.6 5408.9,5238.8 5411.1,5239.2 5412.8,5239.7
  region net INV+: 6060.9,4481.4 6057,4477.5 6056.1,4478 6054.3,4478.5 6052.2,4478.9 6049.9,4479.1 6059.3,4488.5 6059.5,4486.2 6060,4484.1 6060.4,4482.3
  region net INV-: 6073.4,4477.5 6069.5,4481.4 6070,4482.3 6070.5,4484.1 6070.9,4486.2 6071.1,4488.5 6080.5,4479.1 6078.3,4478.9 6076.1,4478.5 6074.4,4478
  region net INV+: 5413.8,4687 5417.7,4683.1 5417.2,4682.1 5416.7,4680.4 5416.3,4678.2 5416.1,4676 5406.7,4685.4 5408.9,4685.6 5411.1,4686 5412.8,4686.5
  region net INV-: 5426.3,4683.1 5430.2,4687 5431.1,4686.5 5432.9,4686 5435,4685.6 5437.3,4685.4 5427.9,4676 5427.7,4678.2 5427.3,4680.4 5426.8,4682.1
  region net INU+: 6060.9,3931.2 6057,3927.3 6056.1,3927.8 6054.3,3928.3 6052.2,3928.7 6049.9,3928.9 6059.3,3938.3 6059.5,3936.1 6060,3933.9 6060.4,3932.2
  region net INU-: 6073.4,3927.3 6069.5,3931.2 6070,3932.2 6070.5,3933.9 6070.9,3936.1 6071.1,3938.3 6080.5,3928.9 6078.3,3928.7 6076.1,3928.3 6074.4,3927.8
  region net INU-: 5426.3,4131.9 5430.2,4135.8 5431.1,4135.3 5432.9,4134.8 5435,4134.4 5437.3,4134.2 5427.9,4124.8 5427.7,4127 5427.3,4129.2 5426.8,4130.9
  region net INU+: 5413.8,4135.8 5417.7,4131.9 5417.2,4130.9 5416.7,4129.2 5416.3,4127 5416.1,4124.8 5406.7,4134.2 5408.9,4134.4 5411.1,4134.8 5412.8,4135.3
Bottom Layer:
  region net CAN_L: 3996.5,5860.3 3996.5,5850.3 3994.5,5850.1 3992.4,5849.4 3990.4,5848.5 3988.4,5847.2 3986.4,5845.6 3984.4,5843.8 3980.7,5839.9 3977.2,5835.7 3974.1,5831.7 3971.3,5828.2 3969,5825.8 3969,5884.8 3971.3,5882.4 3974.1,5878.9 3977.2,5874.9 3980.7,5870.7 3984.4,5866.8 3986.4,5865 3988.4,5863.4 3990.4,5862.1 3992.4,5861.2 3994.5,5860.5
  region net CAN_H: 4027.1,5850.3 4027.1,5860.3 4029.2,5860.5 4031.3,5861.2 4033.3,5862.1 4035.3,5863.4 4037.3,5865 4039.2,5866.8 4043,5870.7 4046.5,5874.9 4049.6,5878.9 4052.4,5882.4 4054.7,5884.8 4054.7,5825.8 4052.4,5828.2 4049.6,5831.7 4046.5,5835.7 4043,5839.9 4039.2,5843.8 4037.3,5845.6 4035.3,5847.2 4033.3,5848.5 4031.3,5849.4 4029.2,5850.1
  region net CAN_L: 3993.5,5920.4 3990.6,5909.1 ccw(c3974.7,5887.9) 3974.7,5914.4 3988.2,5936.3 ccw(c4014.7,5936.3)
  region net CAN_H: 4033,5909.1 4030.1,5920.4 ccw(c4008.9,5936.3) 4035.4,5936.3 4048.9,5914.4 ccw(c4048.9,5887.9)
  region net GND_ESC: 3769.2,5158.7 3769.2,5208.7 3773.4,5208.9 3778,5209.5 3782.7,5210.5 3787.3,5211.7 3791.7,5213.2 3795.7,5214.9 3799.1,5216.6 3801.6,5218.5 3801.6,5148.9 3799.1,5150.7 3795.7,5152.5 3791.7,5154.2 3787.3,5155.6 3782.7,5156.9 3778,5157.9 3773.4,5158.5
  region net GND_ESC: 3722.2,5158.7 ccw(c3722.2,4908.7) 3572.2,5108.7 3547.2,5182.7 3572.2,5258.7 ccw(c3722.2,5458.7) 3722.2,5208.7
  region net GND_ESC: 3572.2,5729.4 3522.2,5729.4 3522,5733.7 3521.4,5738.2 3520.4,5742.9 3519.2,5747.6 3517.7,5752 3516.1,5756 3514.3,5759.3 3512.5,5761.9 3582,5761.9 3580.2,5759.3 3578.4,5756 3576.8,5752 3575.3,5747.6 3574,5742.9 3573.1,5738.2 3572.5,5733.7
  region net GND_ESC: 3522.2,4638 3572.2,4638 3572.5,4633.7 3573.1,4629.2 3574,4624.5 3575.3,4619.8 3576.8,4615.4 3578.4,4611.4 3580.2,4608.1 3582,4605.5 3512.5,4605.5 3514.3,4608.1 3516.1,4611.4 3517.7,4615.4 3519.2,4619.8 3520.4,4624.5 3521.4,4629.2 3522,4633.7
  region net GND_ETH: 3576.6,4354.2 3526.6,4354.2 3526.4,4358.4 3526,4362.9 3525.3,4367.4 3524.4,4371.7 3523.4,4375.7 3522.2,4379.2 3521,4382 3519.7,4383.9 3583.5,4383.9 3582.2,4382 3580.9,4379.2 3579.8,4375.7 3578.7,4371.7 3577.9,4367.4 3577.2,4362.9 3576.7,4358.4
  region net GND_ETH: 3526.6,3860.1 3576.6,3860.1 3576.7,3855.8 3577.2,3851.3 3577.9,3846.8 3578.7,3842.5 3579.8,3838.5 3580.9,3835 3582.2,3832.2 3583.5,3830.3 3519.7,3830.3 3521,3832.2 3522.2,3835 3523.4,3838.5 3524.4,3842.5 3525.3,3846.8 3526,3851.3 3526.4,3855.8
  region net ETH0.RXD1: 4019.8,3946.2 4024.3,3946.2 ccw(c4031.7,3946.2) 4027.7,3940 4016.4,3940 ccw(c4012.4,3946.2)
  region net ETH0.RXD1: 4028.4,3949.3 4025.2,3952.5 4025.6,3953.4 4025.9,3955.2 4026.5,3960 4035.9,3950.6 4031.1,3950.1 4029.3,3949.7

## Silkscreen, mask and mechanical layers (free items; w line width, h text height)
Top Silkscreen Layer:
  lines w10: 3854.3,5702.5 ccw(c3893.7,5702.5) 3893.7,5663.1 4267.7,5663.1 ccw(c4267.7,5702.5) 4307.1,5702.5 4307.1,5800.9 ; 3854.4,5702.5 3854.4,5800.9 ; 4319.7,5800.9 4319.7,5702.5 ccw(c4359.1,5702.5) 4359.1,5663.1 4870.9,5663.1 ccw(c4870.9,5702.5) 4910.3,5702.5 ; 4910.3,5701.8 4910.3,5800.2 ; 4924.3,5801.6 4924.3,5703.2 ccw(c4963.7,5703.2) 4963.7,5663.8 ; 4963.7,5663.9 5613.3,5663.1 ccw(c5613.3,5702.5) 5652.7,5702.5 5652.7,5800.9 ; 5665.2,5704 ccw(c5704.6,5704) 5704.6,5664.6 6492,5664.6 ccw(c6492,5704) 6531.4,5704 ; 5665.3,5704 5665.3,5802.4 ; 6531.4,5703.2 6531.4,5801.6
  text "SPI" at 6039.3,5720.9 h80
  text "CAN" at 4007.1,5720.4 h80
  text "ADC" at 4537.9,5720.4 h80
  text "ABZ" at 5206.7,5720.2 h80
  text "L" at 3924.9,5667.9 h60
  text "H" at 4058.6,5667.9 h60
  text "G" at 4198,5667.9 h60
  text "IN6" at 4638.6,5667.9 h60
  text "AG" at 4778.5,5667.9 h60
  text "CS" at 5840.1,5667.9 h60
  text "MOSI" at 5943.4,5667.9 h60
  text "MISO" at 6111.9,5667.9 h60
  text "CLK" at 6278.1,5667.9 h60
  text "G" at 6422.4,5667.9 h60
  text "A" at 5155,5667.1 h60
  text "B" at 5290.5,5666.8 h60
  text "Z" at 5416.7,5667.1 h60
  text "G" at 5543.6,5667.1 h60
  text "VCC" at 4353.8,5663.9 h60
  text "IN8" at 4500.8,5663.9 h60
  text "VCC" at 5699.4,5663.9 h60
  text "VCC" at 4958.4,5663.2 h60
Top Solder Mask Layer:
  lines w90: 5932.3,3976.7 5932.3,4081.8 ; 5932.3,4527.9 5932.3,4633 ; 5932.3,5079.1 5932.3,5184.2
  text "AspireROS2@gmail.com" at 3997.5,5476.7 h120
  text "AspireROS2@gmail.com" at 4464.5,3019.6 h120
Bottom Solder Mask Layer:
  text "Ethernet for Control Automation Technology" at 5948,5958.5 h120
